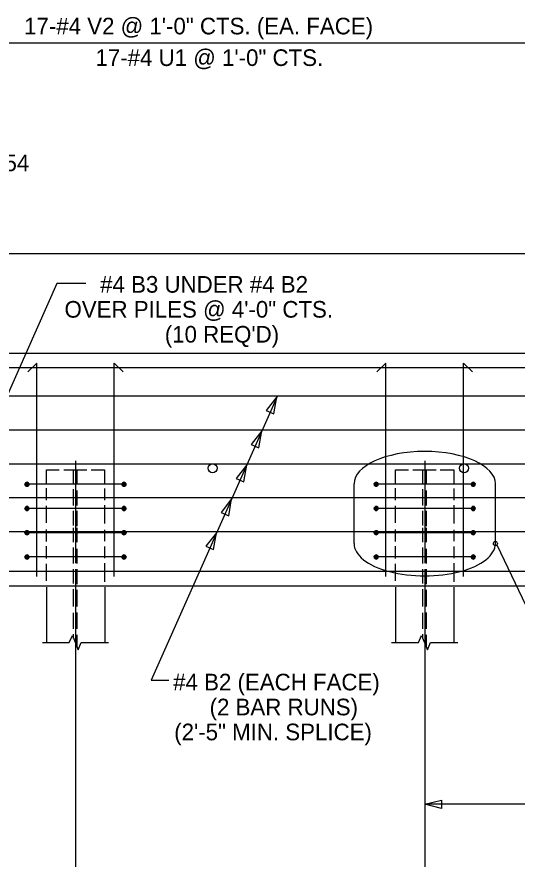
# Model space of a CAD drawing. Extents: x -41 to 191, y -168 to 6.
# Drawn here: x 20.21 to 28.81, y -40.55 to -26.08 of the extents above; entities that cross this region are included whole.
import ezdxf

# ---------------------------------------------------------------- set-up
doc = ezdxf.new("R2010")
doc.units = 0
for name, color, linetype in [('Arrowhead Terminators CELL', 7, 'Continuous'), ('Dimension Lines', 7, 'Continuous'), ('Dimension Lines CELL', 7, 'Continuous'), ('Mis Object Lines', 7, 'Continuous'), ('Mis Object Lines Hidden', 7, 'Continuous'), ('Rebar Lines', 7, 'Continuous'), ('Rebar Lines CELL', 7, 'Continuous'), ('Text', 7, 'Continuous')]:
    doc.layers.add(name, color=color, linetype=linetype)

msp = doc.modelspace()

# ---------------------------------------------------------------- linework, layer by layer
at = {"layer": 'Arrowhead Terminators CELL'}
for points in [[(24.679, -32.61), (24.497, -32.843), (24.628, -32.901)], [(24.42, -33.193), (24.238, -33.426), (24.369, -33.484)], [(24.161, -33.777), (23.979, -34.009), (24.11, -34.067)], [(23.902, -34.36), (23.72, -34.593), (23.851, -34.651)], [(23.643, -34.943), (23.461, -35.176), (23.592, -35.234)], [(27.219, -39.61), (27.505, -39.538), (27.505, -39.681)]]:
    msp.add_lwpolyline(points, close=True, dxfattribs=at)
at = {"layer": 'Dimension Lines'}
for p, q in [((16.318, -26.52), (32.337, -26.52)), ((20.898, -30.66), (19.574, -33.641)), ((21.398, -30.66), (20.898, -30.66)), ((26.004, -35.129), (26.004, -34.102)), ((28.434, -35.129), (28.434, -34.102)), ((28.46, -35.153), (29.319, -36.963)), ((21.219, -35.86), (21.219, -42.485)), ((27.219, -35.86), (27.219, -42.157)), ((32.837, -39.61), (27.219, -39.61))]:
    msp.add_line(p, q, dxfattribs=at)
msp.add_lwpolyline([(24.687, -32.591), (22.518, -37.478), (22.82, -37.478)], dxfattribs=at)
for centre, start_param, end_param in [((27.219, -34.102), 3.141593, 6.283185), ((27.219, -35.129), 0, 3.141593)]:
    msp.add_ellipse(centre, major_axis=(-1.215, 0), ratio=0.457627, start_param=start_param, end_param=end_param, dxfattribs=at)
at = {"layer": 'Dimension Lines CELL'}
msp.add_circle((28.434, -35.129), 0.0353, dxfattribs=at)
at = {"layer": 'Mis Object Lines'}
for p, q in [((43.116, -30.152), (16.026, -30.152)), ((47.445, -35.86), (12.601, -35.86))]:
    msp.add_line(p, q, dxfattribs=at)
at = {"layer": 'Mis Object Lines Hidden'}
msp.add_line((49.619, -31.86), (12.601, -31.86), dxfattribs=at)
at = {"layer": 'Rebar Lines'}
for p, q in [((53.096, -32.111), (14.053, -32.111)), ((20.552, -32.027), (20.399, -32.18)), ((20.552, -35.693), (20.552, -32.027)), ((21.886, -35.693), (21.886, -32.027)), ((21.886, -32.027), (22.039, -32.18)), ((26.552, -32.027), (26.399, -32.18)), ((26.552, -35.693), (26.552, -32.027)), ((27.886, -35.693), (27.886, -32.027)), ((27.886, -32.027), (28.039, -32.18)), ((13.513, -32.591), (31.532, -32.591)), ((13.513, -33.174), (31.532, -33.174)), ((21.219, -33.709), (21.219, -35.465)), ((27.219, -33.709), (27.219, -35.465)), ((13.513, -33.757), (31.532, -33.757)), ((21.187, -34.103), (21.187, -33.86)), ((21.25, -34.108), (21.25, -33.86)), ((27.187, -34.103), (27.187, -33.86)), ((27.25, -34.108), (27.25, -33.86)), ((21.187, -34.474), (21.187, -34.196)), ((21.25, -34.474), (21.25, -34.219)), ((27.187, -34.474), (27.187, -34.196)), ((27.25, -34.474), (27.25, -34.219)), ((13.513, -34.34), (31.532, -34.34)), ((21.187, -34.817), (21.187, -34.567)), ((21.25, -34.829), (21.25, -34.567)), ((27.187, -34.817), (27.187, -34.567)), ((27.25, -34.829), (27.25, -34.567)), ((21.187, -35.103), (21.187, -34.86)), ((21.25, -35.108), (21.25, -34.86)), ((27.187, -35.103), (27.187, -34.86)), ((27.25, -35.108), (27.25, -34.86)), ((13.513, -34.924), (31.532, -34.924)), ((21.187, -35.474), (21.187, -35.196)), ((21.25, -35.474), (21.25, -35.219)), ((27.187, -35.474), (27.187, -35.196)), ((27.25, -35.474), (27.25, -35.219)), ((53.096, -35.61), (13.96, -35.61)), ((21.187, -35.817), (21.187, -35.567)), ((21.219, -35.57), (21.219, -35.86)), ((21.25, -35.829), (21.25, -35.567)), ((27.187, -35.817), (27.187, -35.567)), ((27.219, -35.57), (27.219, -35.86)), ((27.25, -35.829), (27.25, -35.567)), ((20.718, -35.877), (20.718, -36.829)), ((21.72, -35.877), (21.72, -36.829)), ((26.718, -35.877), (26.718, -36.829)), ((27.72, -35.877), (27.72, -36.829)), ((21.187, -36.212), (21.187, -35.916)), ((21.219, -35.93), (21.219, -37.136)), ((21.25, -36.212), (21.25, -35.922)), ((27.187, -36.212), (27.187, -35.916)), ((27.219, -35.93), (27.219, -37.136)), ((27.25, -36.212), (27.25, -35.922)), ((21.187, -36.595), (21.187, -36.322)), ((21.25, -36.595), (21.25, -36.317)), ((27.187, -36.595), (27.187, -36.322)), ((27.25, -36.595), (27.25, -36.317)), ((21.187, -36.763), (21.187, -36.689)), ((21.25, -36.913), (21.25, -36.7)), ((27.187, -36.763), (27.187, -36.689)), ((27.25, -36.913), (27.25, -36.7))]:
    msp.add_line(p, q, dxfattribs=at)
for points in [[(20.718, -34.094), (20.718, -33.86), (20.941, -33.86)], [(21.017, -33.86), (21.416, -33.86)], [(21.486, -33.86), (21.718, -33.86), (21.718, -34.106)], [(26.718, -34.094), (26.718, -33.86), (26.941, -33.86)], [(27.017, -33.86), (27.416, -33.86)], [(27.486, -33.86), (27.718, -33.86), (27.718, -34.106)], [(20.718, -34.384), (20.718, -34.176)], [(21.718, -34.182), (21.718, -34.381)], [(26.718, -34.384), (26.718, -34.176)], [(27.718, -34.182), (27.718, -34.381)], [(20.718, -34.771), (20.718, -34.48)], [(21.718, -34.467), (21.718, -34.787)], [(26.718, -34.771), (26.718, -34.48)], [(27.718, -34.467), (27.718, -34.787)], [(20.718, -35.094), (20.718, -34.886)], [(21.718, -34.892), (21.718, -35.091)], [(26.718, -35.094), (26.718, -34.886)], [(27.718, -34.892), (27.718, -35.091)], [(20.718, -35.384), (20.718, -35.176)], [(21.718, -35.182), (21.718, -35.381)], [(26.718, -35.384), (26.718, -35.176)], [(27.718, -35.182), (27.718, -35.381)], [(21.718, -35.467), (21.718, -35.787)], [(27.718, -35.467), (27.718, -35.787)], [(20.718, -35.771), (20.718, -35.48)], [(26.718, -35.771), (26.718, -35.48)], [(20.649, -36.829), (21.111, -36.829), (21.165, -36.71), (21.267, -36.954), (21.319, -36.829), (21.786, -36.829)], [(26.649, -36.829), (27.111, -36.829), (27.165, -36.71), (27.267, -36.954), (27.319, -36.829), (27.786, -36.829)]]:
    msp.add_lwpolyline(points, dxfattribs=at)
at = {"layer": 'Rebar Lines CELL'}
for p, q in [((22.052, -34.11), (20.386, -34.11)), ((28.052, -34.11), (26.386, -34.11)), ((22.052, -34.527), (20.386, -34.527)), ((28.052, -34.527), (26.386, -34.527)), ((22.052, -34.943), (20.386, -34.943)), ((28.052, -34.943), (26.386, -34.943)), ((22.052, -35.36), (20.386, -35.36)), ((28.052, -35.36), (26.386, -35.36))]:
    msp.add_line(p, q, dxfattribs=at)
for points in [[(20.386, -34.075), (20.372, -34.077), (20.361, -34.085), (20.353, -34.096), (20.35, -34.11), (20.353, -34.123), (20.361, -34.135), (20.372, -34.142), (20.386, -34.145), (20.399, -34.142), (20.41, -34.135), (20.418, -34.123), (20.421, -34.11), (20.418, -34.096), (20.411, -34.085), (20.399, -34.077), (20.386, -34.075), (20.386, -34.11), (20.386, -34.145), (20.372, -34.142), (20.386, -34.11), (20.361, -34.135), (20.353, -34.123), (20.386, -34.11), (20.35, -34.11), (20.353, -34.096), (20.386, -34.11), (20.361, -34.085), (20.372, -34.077), (20.386, -34.11), (20.399, -34.077), (20.411, -34.085), (20.386, -34.11), (20.418, -34.096), (20.421, -34.11), (20.386, -34.11), (20.418, -34.123), (20.41, -34.135), (20.386, -34.11), (20.399, -34.142)], [(22.052, -34.075), (22.039, -34.077), (22.027, -34.085), (22.02, -34.096), (22.017, -34.11), (22.02, -34.123), (22.027, -34.135), (22.039, -34.142), (22.052, -34.145), (22.066, -34.142), (22.077, -34.135), (22.085, -34.123), (22.088, -34.11), (22.085, -34.096), (22.077, -34.085), (22.066, -34.077), (22.052, -34.075), (22.052, -34.11), (22.052, -34.145), (22.039, -34.142), (22.052, -34.11), (22.027, -34.135), (22.02, -34.123), (22.052, -34.11), (22.017, -34.11), (22.02, -34.096), (22.052, -34.11), (22.027, -34.085), (22.039, -34.077), (22.052, -34.11), (22.066, -34.077), (22.077, -34.085), (22.052, -34.11), (22.085, -34.096), (22.088, -34.11), (22.052, -34.11), (22.085, -34.123), (22.077, -34.135), (22.052, -34.11), (22.066, -34.142)], [(26.386, -34.075), (26.372, -34.077), (26.361, -34.085), (26.353, -34.096), (26.35, -34.11), (26.353, -34.123), (26.361, -34.135), (26.372, -34.142), (26.386, -34.145), (26.399, -34.142), (26.41, -34.135), (26.418, -34.123), (26.421, -34.11), (26.418, -34.096), (26.411, -34.085), (26.399, -34.077), (26.386, -34.075), (26.386, -34.11), (26.386, -34.145), (26.372, -34.142), (26.386, -34.11), (26.361, -34.135), (26.353, -34.123), (26.386, -34.11), (26.35, -34.11), (26.353, -34.096), (26.386, -34.11), (26.361, -34.085), (26.372, -34.077), (26.386, -34.11), (26.399, -34.077), (26.411, -34.085), (26.386, -34.11), (26.418, -34.096), (26.421, -34.11), (26.386, -34.11), (26.418, -34.123), (26.41, -34.135), (26.386, -34.11), (26.399, -34.142)], [(28.052, -34.075), (28.039, -34.077), (28.027, -34.085), (28.02, -34.096), (28.017, -34.11), (28.02, -34.123), (28.027, -34.135), (28.039, -34.142), (28.052, -34.145), (28.066, -34.142), (28.077, -34.135), (28.085, -34.123), (28.088, -34.11), (28.085, -34.096), (28.077, -34.085), (28.066, -34.077), (28.052, -34.075), (28.052, -34.11), (28.052, -34.145), (28.039, -34.142), (28.052, -34.11), (28.027, -34.135), (28.02, -34.123), (28.052, -34.11), (28.017, -34.11), (28.02, -34.096), (28.052, -34.11), (28.027, -34.085), (28.039, -34.077), (28.052, -34.11), (28.066, -34.077), (28.077, -34.085), (28.052, -34.11), (28.085, -34.096), (28.088, -34.11), (28.052, -34.11), (28.085, -34.123), (28.077, -34.135), (28.052, -34.11), (28.066, -34.142)], [(20.386, -34.491), (20.372, -34.494), (20.361, -34.502), (20.353, -34.513), (20.35, -34.527), (20.353, -34.54), (20.361, -34.551), (20.372, -34.559), (20.386, -34.562), (20.399, -34.559), (20.41, -34.551), (20.418, -34.54), (20.421, -34.527), (20.418, -34.513), (20.411, -34.502), (20.399, -34.494), (20.386, -34.491), (20.386, -34.527), (20.386, -34.562), (20.372, -34.559), (20.386, -34.527), (20.361, -34.551), (20.353, -34.54), (20.386, -34.527), (20.35, -34.527), (20.353, -34.513), (20.386, -34.527), (20.361, -34.502), (20.372, -34.494), (20.386, -34.527), (20.399, -34.494), (20.411, -34.502), (20.386, -34.527), (20.418, -34.513), (20.421, -34.527), (20.386, -34.527), (20.418, -34.54), (20.41, -34.551), (20.386, -34.527), (20.399, -34.559)], [(22.052, -34.491), (22.039, -34.494), (22.027, -34.502), (22.02, -34.513), (22.017, -34.527), (22.02, -34.54), (22.027, -34.551), (22.039, -34.559), (22.052, -34.562), (22.066, -34.559), (22.077, -34.551), (22.085, -34.54), (22.088, -34.527), (22.085, -34.513), (22.077, -34.502), (22.066, -34.494), (22.052, -34.491), (22.052, -34.527), (22.052, -34.562), (22.039, -34.559), (22.052, -34.527), (22.027, -34.551), (22.02, -34.54), (22.052, -34.527), (22.017, -34.527), (22.02, -34.513), (22.052, -34.527), (22.027, -34.502), (22.039, -34.494), (22.052, -34.527), (22.066, -34.494), (22.077, -34.502), (22.052, -34.527), (22.085, -34.513), (22.088, -34.527), (22.052, -34.527), (22.085, -34.54), (22.077, -34.551), (22.052, -34.527), (22.066, -34.559)], [(26.386, -34.491), (26.372, -34.494), (26.361, -34.502), (26.353, -34.513), (26.35, -34.527), (26.353, -34.54), (26.361, -34.551), (26.372, -34.559), (26.386, -34.562), (26.399, -34.559), (26.41, -34.551), (26.418, -34.54), (26.421, -34.527), (26.418, -34.513), (26.411, -34.502), (26.399, -34.494), (26.386, -34.491), (26.386, -34.527), (26.386, -34.562), (26.372, -34.559), (26.386, -34.527), (26.361, -34.551), (26.353, -34.54), (26.386, -34.527), (26.35, -34.527), (26.353, -34.513), (26.386, -34.527), (26.361, -34.502), (26.372, -34.494), (26.386, -34.527), (26.399, -34.494), (26.411, -34.502), (26.386, -34.527), (26.418, -34.513), (26.421, -34.527), (26.386, -34.527), (26.418, -34.54), (26.41, -34.551), (26.386, -34.527), (26.399, -34.559)], [(28.052, -34.491), (28.039, -34.494), (28.027, -34.502), (28.02, -34.513), (28.017, -34.527), (28.02, -34.54), (28.027, -34.551), (28.039, -34.559), (28.052, -34.562), (28.066, -34.559), (28.077, -34.551), (28.085, -34.54), (28.088, -34.527), (28.085, -34.513), (28.077, -34.502), (28.066, -34.494), (28.052, -34.491), (28.052, -34.527), (28.052, -34.562), (28.039, -34.559), (28.052, -34.527), (28.027, -34.551), (28.02, -34.54), (28.052, -34.527), (28.017, -34.527), (28.02, -34.513), (28.052, -34.527), (28.027, -34.502), (28.039, -34.494), (28.052, -34.527), (28.066, -34.494), (28.077, -34.502), (28.052, -34.527), (28.085, -34.513), (28.088, -34.527), (28.052, -34.527), (28.085, -34.54), (28.077, -34.551), (28.052, -34.527), (28.066, -34.559)], [(20.386, -34.908), (20.372, -34.911), (20.361, -34.918), (20.353, -34.93), (20.35, -34.943), (20.353, -34.957), (20.361, -34.968), (20.372, -34.976), (20.386, -34.978), (20.399, -34.976), (20.41, -34.968), (20.418, -34.957), (20.421, -34.943), (20.418, -34.93), (20.411, -34.918), (20.399, -34.911), (20.386, -34.908), (20.386, -34.943), (20.386, -34.978), (20.372, -34.976), (20.386, -34.943), (20.361, -34.968), (20.353, -34.957), (20.386, -34.943), (20.35, -34.943), (20.353, -34.93), (20.386, -34.943), (20.361, -34.918), (20.372, -34.911), (20.386, -34.943), (20.399, -34.911), (20.411, -34.918), (20.386, -34.943), (20.418, -34.93), (20.421, -34.943), (20.386, -34.943), (20.418, -34.957), (20.41, -34.968), (20.386, -34.943), (20.399, -34.976)], [(22.052, -34.908), (22.039, -34.911), (22.027, -34.918), (22.02, -34.93), (22.017, -34.943), (22.02, -34.957), (22.027, -34.968), (22.039, -34.976), (22.052, -34.978), (22.066, -34.976), (22.077, -34.968), (22.085, -34.957), (22.088, -34.943), (22.085, -34.93), (22.077, -34.918), (22.066, -34.911), (22.052, -34.908), (22.052, -34.943), (22.052, -34.978), (22.039, -34.976), (22.052, -34.943), (22.027, -34.968), (22.02, -34.957), (22.052, -34.943), (22.017, -34.943), (22.02, -34.93), (22.052, -34.943), (22.027, -34.918), (22.039, -34.911), (22.052, -34.943), (22.066, -34.911), (22.077, -34.918), (22.052, -34.943), (22.085, -34.93), (22.088, -34.943), (22.052, -34.943), (22.085, -34.957), (22.077, -34.968), (22.052, -34.943), (22.066, -34.976)], [(26.386, -34.908), (26.372, -34.911), (26.361, -34.918), (26.353, -34.93), (26.35, -34.943), (26.353, -34.957), (26.361, -34.968), (26.372, -34.976), (26.386, -34.978), (26.399, -34.976), (26.41, -34.968), (26.418, -34.957), (26.421, -34.943), (26.418, -34.93), (26.411, -34.918), (26.399, -34.911), (26.386, -34.908), (26.386, -34.943), (26.386, -34.978), (26.372, -34.976), (26.386, -34.943), (26.361, -34.968), (26.353, -34.957), (26.386, -34.943), (26.35, -34.943), (26.353, -34.93), (26.386, -34.943), (26.361, -34.918), (26.372, -34.911), (26.386, -34.943), (26.399, -34.911), (26.411, -34.918), (26.386, -34.943), (26.418, -34.93), (26.421, -34.943), (26.386, -34.943), (26.418, -34.957), (26.41, -34.968), (26.386, -34.943), (26.399, -34.976)], [(28.052, -34.908), (28.039, -34.911), (28.027, -34.918), (28.02, -34.93), (28.017, -34.943), (28.02, -34.957), (28.027, -34.968), (28.039, -34.976), (28.052, -34.978), (28.066, -34.976), (28.077, -34.968), (28.085, -34.957), (28.088, -34.943), (28.085, -34.93), (28.077, -34.918), (28.066, -34.911), (28.052, -34.908), (28.052, -34.943), (28.052, -34.978), (28.039, -34.976), (28.052, -34.943), (28.027, -34.968), (28.02, -34.957), (28.052, -34.943), (28.017, -34.943), (28.02, -34.93), (28.052, -34.943), (28.027, -34.918), (28.039, -34.911), (28.052, -34.943), (28.066, -34.911), (28.077, -34.918), (28.052, -34.943), (28.085, -34.93), (28.088, -34.943), (28.052, -34.943), (28.085, -34.957), (28.077, -34.968), (28.052, -34.943), (28.066, -34.976)], [(20.386, -35.325), (20.372, -35.327), (20.361, -35.335), (20.353, -35.346), (20.35, -35.36), (20.353, -35.373), (20.361, -35.385), (20.372, -35.392), (20.386, -35.395), (20.399, -35.392), (20.41, -35.385), (20.418, -35.373), (20.421, -35.36), (20.418, -35.346), (20.411, -35.335), (20.399, -35.327), (20.386, -35.325), (20.386, -35.36), (20.386, -35.395), (20.372, -35.392), (20.386, -35.36), (20.361, -35.385), (20.353, -35.373), (20.386, -35.36), (20.35, -35.36), (20.353, -35.346), (20.386, -35.36), (20.361, -35.335), (20.372, -35.327), (20.386, -35.36), (20.399, -35.327), (20.411, -35.335), (20.386, -35.36), (20.418, -35.346), (20.421, -35.36), (20.386, -35.36), (20.418, -35.373), (20.41, -35.385), (20.386, -35.36), (20.399, -35.392)], [(22.052, -35.325), (22.039, -35.327), (22.027, -35.335), (22.02, -35.346), (22.017, -35.36), (22.02, -35.373), (22.027, -35.385), (22.039, -35.392), (22.052, -35.395), (22.066, -35.392), (22.077, -35.385), (22.085, -35.373), (22.088, -35.36), (22.085, -35.346), (22.077, -35.335), (22.066, -35.327), (22.052, -35.325), (22.052, -35.36), (22.052, -35.395), (22.039, -35.392), (22.052, -35.36), (22.027, -35.385), (22.02, -35.373), (22.052, -35.36), (22.017, -35.36), (22.02, -35.346), (22.052, -35.36), (22.027, -35.335), (22.039, -35.327), (22.052, -35.36), (22.066, -35.327), (22.077, -35.335), (22.052, -35.36), (22.085, -35.346), (22.088, -35.36), (22.052, -35.36), (22.085, -35.373), (22.077, -35.385), (22.052, -35.36), (22.066, -35.392)], [(26.386, -35.325), (26.372, -35.327), (26.361, -35.335), (26.353, -35.346), (26.35, -35.36), (26.353, -35.373), (26.361, -35.385), (26.372, -35.392), (26.386, -35.395), (26.399, -35.392), (26.41, -35.385), (26.418, -35.373), (26.421, -35.36), (26.418, -35.346), (26.411, -35.335), (26.399, -35.327), (26.386, -35.325), (26.386, -35.36), (26.386, -35.395), (26.372, -35.392), (26.386, -35.36), (26.361, -35.385), (26.353, -35.373), (26.386, -35.36), (26.35, -35.36), (26.353, -35.346), (26.386, -35.36), (26.361, -35.335), (26.372, -35.327), (26.386, -35.36), (26.399, -35.327), (26.411, -35.335), (26.386, -35.36), (26.418, -35.346), (26.421, -35.36), (26.386, -35.36), (26.418, -35.373), (26.41, -35.385), (26.386, -35.36), (26.399, -35.392)], [(28.052, -35.325), (28.039, -35.327), (28.027, -35.335), (28.02, -35.346), (28.017, -35.36), (28.02, -35.373), (28.027, -35.385), (28.039, -35.392), (28.052, -35.395), (28.066, -35.392), (28.077, -35.385), (28.085, -35.373), (28.088, -35.36), (28.085, -35.346), (28.077, -35.335), (28.066, -35.327), (28.052, -35.325), (28.052, -35.36), (28.052, -35.395), (28.039, -35.392), (28.052, -35.36), (28.027, -35.385), (28.02, -35.373), (28.052, -35.36), (28.017, -35.36), (28.02, -35.346), (28.052, -35.36), (28.027, -35.335), (28.039, -35.327), (28.052, -35.36), (28.066, -35.327), (28.077, -35.335), (28.052, -35.36), (28.085, -35.346), (28.088, -35.36), (28.052, -35.36), (28.085, -35.373), (28.077, -35.385), (28.052, -35.36), (28.066, -35.392)]]:
    msp.add_lwpolyline(points, dxfattribs=at)
for centre in [(23.574, -33.834), (27.896, -33.834)]:
    msp.add_circle(centre, 0.0773, dxfattribs=at)

# ---------------------------------------------------------------- texts
at = {"layer": 'Text'}
for s, p in [('17-#4 V2 @ 1\'-0" CTS. (EA. FACE)', (20.336, -26.377)), ('17-#4 U1 @ 1\'-0" CTS.', (21.562, -26.92)), ('EL. 181.54', (18.574, -28.729)), ('#4 B3 UNDER #4 B2', (21.642, -30.817)), ('OVER PILES @ 4\'-0" CTS.', (21.03, -31.246)), ("(10 REQ'D)", (22.753, -31.675)), ('#4 B2 (EACH FACE)', (22.897, -37.653)), ('(2 BAR RUNS)', (23.523, -38.082)), ('(2\'-5" MIN. SPLICE)', (22.915, -38.511))]:
    msp.add_text(s, height=0.286, dxfattribs=at).set_placement(p)

doc.saveas('drawing.dxf')
